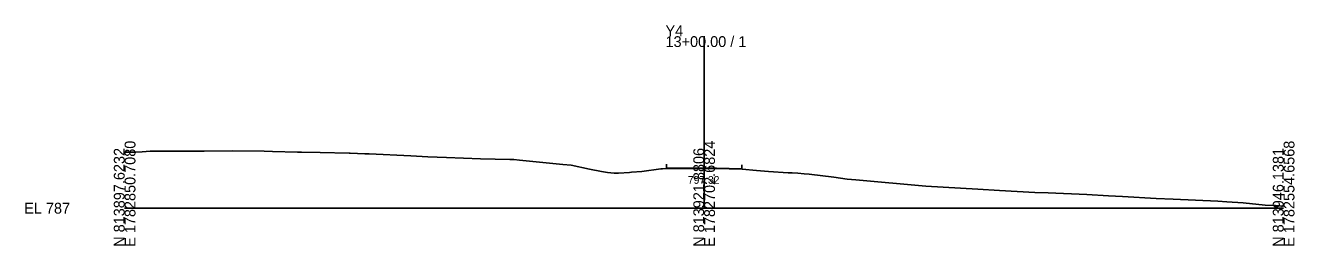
# Model space of a CAD drawing. Extents: x -26 to 3903, y -10 to 9562.
# Drawn here: x -25.7 to 302.8, y 4990.3 to 5047.4 of the extents above; entities that cross this region are included whole.
import ezdxf

# ---------------------------------------------------------------- set-up
doc = ezdxf.new("R2010")
doc.units = 0
for name, color, linetype in [('Exist Cross Section Cell', 7, 'Continuous'), ('Exist XS Center Line Elevation Label', 7, 'Continuous'), ('Exist XS Ground Line', 7, 'Continuous'), ('Prop XS EOT Tick Mark', 7, 'Continuous'), ('Prop XS Finish Grade Pavement', 7, 'Continuous')]:
    doc.layers.add(name, color=color, linetype=linetype)

msp = doc.modelspace()

# ---------------------------------------------------------------- linework, layer by layer
at = {"layer": 'Exist Cross Section Cell'}
for p, q in [((150, 5000), (150, 5044.55)), ((0, 5000), (150, 5000)), ((150, 5000), (300, 5000))]:
    msp.add_line(p, q, dxfattribs=at)
at = {"layer": 'Exist XS Ground Line'}
for p, q in [((0, 5014.49), (2.87, 5014.51)), ((2.87, 5014.51), (4.5, 5014.61)), ((4.5, 5014.61), (6.64, 5014.73)), ((6.64, 5014.73), (10.9, 5014.76)), ((10.9, 5014.76), (15.77, 5014.76)), ((15.77, 5014.76), (18.66, 5014.8)), ((18.66, 5014.8), (20.59, 5014.76)), ((20.59, 5014.76), (28.01, 5014.85)), ((28.01, 5014.85), (36.1, 5014.73)), ((36.1, 5014.73), (38.25, 5014.7)), ((38.25, 5014.7), (44.75, 5014.54)), ((44.75, 5014.54), (45.79, 5014.52)), ((45.79, 5014.52), (50.57, 5014.42)), ((50.57, 5014.42), (58.1, 5014.27)), ((58.1, 5014.27), (58.41, 5014.26)), ((58.41, 5014.26), (62.2, 5014.12)), ((62.2, 5014.12), (63.28, 5014.07)), ((63.28, 5014.07), (74.07, 5013.53)), ((74.07, 5013.53), (78.45, 5013.31)), ((78.45, 5013.31), (83.3, 5013.12)), ((83.3, 5013.12), (92.14, 5012.83)), ((92.14, 5012.83), (99.71, 5012.64)), ((99.71, 5012.64), (100.76, 5012.61)), ((100.76, 5012.61), (102.23, 5012.44)), ((102.23, 5012.44), (113.41, 5011.34)), ((113.41, 5011.34), (115.6, 5011.17)), ((115.6, 5011.17), (120.34, 5010.15)), ((120.34, 5010.15), (123.43, 5009.5)), ((133.84, 5009.51), (138.76, 5010.2)), ((138.76, 5010.2), (139.19, 5010.23)), ((139.19, 5010.23), (140.24, 5010.26)), ((140.24, 5010.26), (144.11, 5010.27)), ((144.11, 5010.27), (149.98, 5010.32)), ((149.98, 5010.32), (156.44, 5010.17)), ((156.44, 5010.17), (159.83, 5010.08)), ((123.43, 5009.5), (124.96, 5009.26)), ((124.96, 5009.26), (126.73, 5009.1)), ((126.73, 5009.1), (127.85, 5009.07)), ((127.85, 5009.07), (130.65, 5009.29)), ((130.65, 5009.29), (131.17, 5009.33)), ((131.17, 5009.33), (133.84, 5009.51)), ((159.83, 5010.08), (163.57, 5009.76)), ((163.57, 5009.76), (166.63, 5009.51)), ((166.63, 5009.51), (171.71, 5009.2)), ((171.71, 5009.2), (172.76, 5009.15)), ((172.76, 5009.15), (174.29, 5009.04)), ((174.29, 5009.04), (175.87, 5008.93)), ((175.87, 5008.93), (177.2, 5008.79)), ((177.2, 5008.79), (183.59, 5008.02)), ((183.59, 5008.02), (187.05, 5007.51)), ((187.05, 5007.51), (189.26, 5007.32)), ((189.26, 5007.32), (207.36, 5005.68)), ((207.36, 5005.68), (220.83, 5004.89)), ((220.83, 5004.89), (226.45, 5004.61)), ((226.45, 5004.61), (235.62, 5004.05)), ((235.62, 5004.05), (239.08, 5003.95)), ((239.08, 5003.95), (249.04, 5003.58)), ((249.04, 5003.58), (254.68, 5003.19)), ((254.68, 5003.19), (258.31, 5003.03)), ((258.31, 5003.03), (266.98, 5002.51)), ((266.98, 5002.51), (271.41, 5002.32)), ((271.41, 5002.32), (282.98, 5001.81)), ((282.98, 5001.81), (285.32, 5001.69)), ((285.32, 5001.69), (289.49, 5001.36)), ((289.49, 5001.36), (295.24, 5000.81)), ((295.24, 5000.81), (297.91, 5000.69)), ((297.91, 5000.69), (300, 5000.57))]:
    msp.add_line(p, q, dxfattribs=at)
at = {"layer": 'Prop XS EOT Tick Mark'}
for p, q in [((140.24, 5010.38), (140.24, 5011.38)), ((159.79, 5010.21), (159.79, 5011.21))]:
    msp.add_line(p, q, dxfattribs=at)
at = {"layer": 'Prop XS Finish Grade Pavement'}
for p, q in [((140.24, 5010.38), (144.11, 5010.4)), ((144.11, 5010.4), (149.98, 5010.45)), ((149.98, 5010.45), (156.44, 5010.29)), ((156.44, 5010.29), (159.79, 5010.21))]:
    msp.add_line(p, q, dxfattribs=at)

# ---------------------------------------------------------------- texts
at = {"layer": 'Exist Cross Section Cell'}
for s, p in [('Y4', (140, 5044.55)), ('13+00.00 / 1', (140, 5041.75)), ('EL 787', (-26, 4998.6))]:
    msp.add_text(s, height=2.8, dxfattribs=at).set_placement(p)
for s, p in [('E 1782850.7080', (2.8, 4990)), ('E 1782702.6824', (152.8, 4990)), ('E 1782554.6568', (302.8, 4990)), ('N 813897.6232', (0, 4990)), ('N 813921.8806', (150, 4990)), ('N 813946.1381', (300, 4990))]:
    msp.add_text(s, height=2.8, rotation=90, dxfattribs=at).set_placement(p)
at = {"layer": 'Exist XS Center Line Elevation Label'}
msp.add_text('797.32', height=2, dxfattribs=at).set_placement((145.79, 5006.32))

doc.saveas('drawing.dxf')
